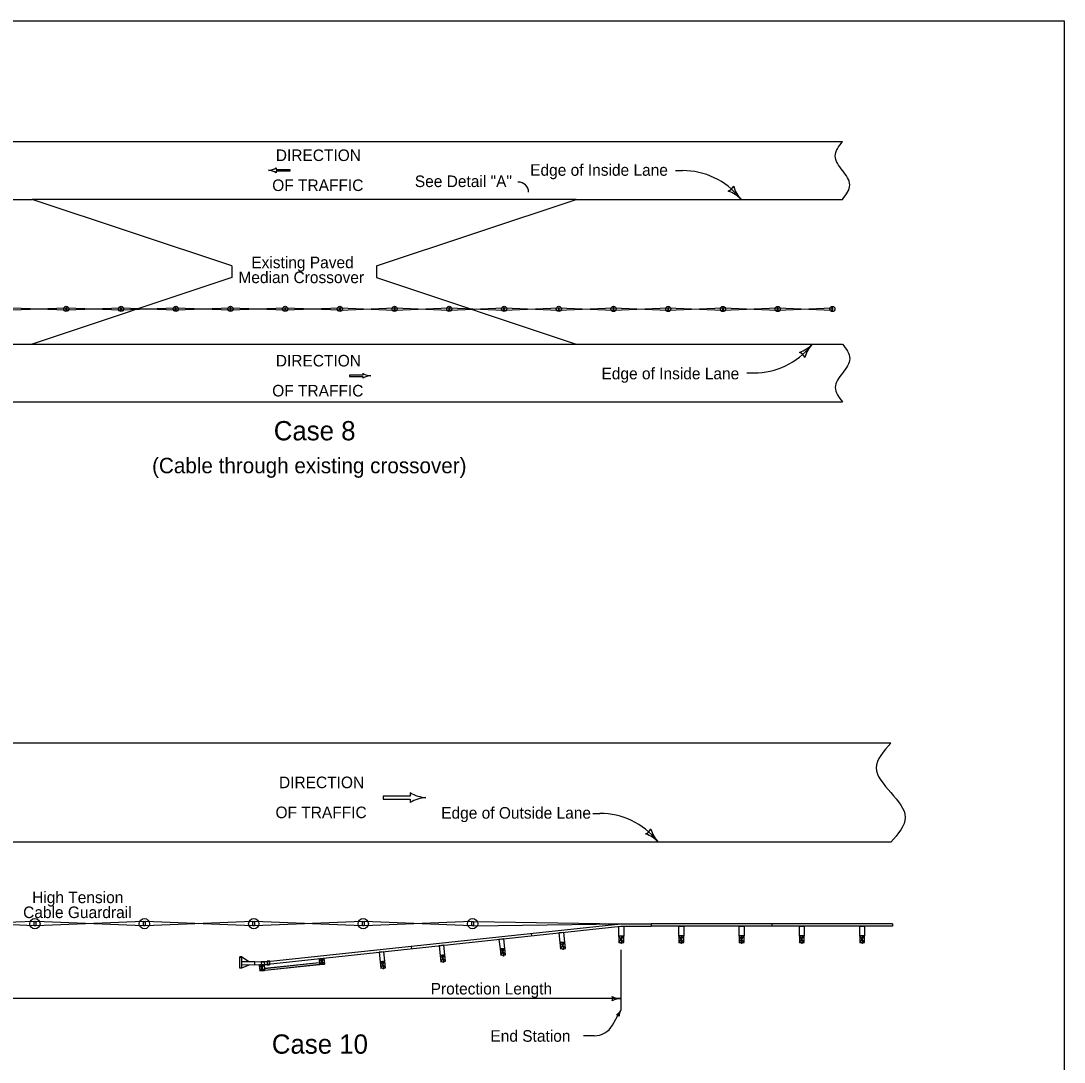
# Model space of a CAD drawing. Extents: x 10133 to 81668, y 7924 to 11018.
# Drawn here: x 15786 to 16868, y 8864 to 9944 of the extents above; entities that cross this region are included whole.
import ezdxf

# ---------------------------------------------------------------- set-up
doc = ezdxf.new("R2010")
doc.units = 0
for name, color, linetype in [('dsnCellElements', 7, 'Continuous'), ('DsnShtRevisedText', 7, 'Continuous'), ('dsnStdDimension', 7, 'Continuous'), ('Level 2', 7, 'Continuous'), ('Level 8', 7, 'Continuous'), ('SheetBorder', 7, 'Continuous')]:
    doc.layers.add(name, color=color, linetype=linetype)

msp = doc.modelspace()

# ---------------------------------------------------------------- linework, layer by layer
at = {"layer": 'dsnCellElements'}
for p, q in [((15777.3, 9644.3), (15833.1, 9646.6)), ((15777.3, 9646.6), (15833.1, 9644.3)), ((15834, 9644.3), (15889.8, 9646.5)), ((15834, 9646.5), (15889.8, 9644.3)), ((15890.7, 9644.3), (15946.5, 9646.5)), ((15890.7, 9646.5), (15946.5, 9644.3)), ((15947.4, 9644.3), (16003.2, 9646.5)), ((15947.4, 9646.5), (16003.2, 9644.3)), ((16004.1, 9644.3), (16059.9, 9646.5)), ((16004.1, 9646.5), (16059.9, 9644.3)), ((16060.8, 9644.3), (16116.6, 9646.5)), ((16060.8, 9646.5), (16116.6, 9644.3)), ((16117.5, 9644.2), (16173.3, 9646.5)), ((16117.5, 9646.5), (16173.3, 9644.2)), ((16174.2, 9644.2), (16230, 9646.5)), ((16174.2, 9646.5), (16230, 9644.2)), ((16230.9, 9644.2), (16286.7, 9646.5)), ((16230.9, 9646.5), (16286.7, 9644.2)), ((16287.6, 9644.2), (16343.4, 9646.5)), ((16287.6, 9646.5), (16343.4, 9644.2)), ((16344.3, 9644.2), (16400.1, 9646.5)), ((16344.3, 9646.5), (16400.1, 9644.2)), ((16401, 9644.2), (16456.8, 9646.5)), ((16401, 9646.5), (16456.8, 9644.2)), ((16457.7, 9644.2), (16513.5, 9646.5)), ((16457.7, 9646.5), (16513.5, 9644.2)), ((16514.4, 9644.2), (16570.2, 9646.5)), ((16514.4, 9646.5), (16570.2, 9644.2)), ((16571.1, 9644.2), (16626.9, 9646.5)), ((16571.1, 9646.5), (16626.9, 9644.2)), ((15800.1, 9005.8), (15688.5, 9010.3)), ((15800.1, 9010.3), (15688.5, 9005.8)), ((15913.5, 9005.8), (15801.9, 9010.3)), ((15913.5, 9010.3), (15801.9, 9005.8)), ((16026.9, 9005.8), (15915.3, 9010.3)), ((16026.9, 9010.3), (15915.3, 9005.8)), ((16140.3, 9005.8), (16028.7, 9010.3)), ((16140.3, 9010.3), (16028.7, 9005.8)), ((16253.7, 9005.8), (16142.1, 9010.3)), ((16253.7, 9010.3), (16142.1, 9005.8)), ((16255.5, 9010.3), (16408.3, 9008)), ((16255.5, 9005.8), (16408.3, 9008))]:
    msp.add_line(p, q, dxfattribs=at)
for points in [[(15833.1, 9646.6), (15833.1, 9644.3), (15834, 9644.3), (15834, 9646.6)], [(15833.1, 9646.5), (15833.1, 9644.3), (15834, 9644.3), (15834, 9646.5)], [(15889.8, 9646.5), (15889.8, 9644.3), (15890.7, 9644.3), (15890.7, 9646.5)], [(15889.8, 9646.5), (15889.8, 9644.3), (15890.7, 9644.3), (15890.7, 9646.5)], [(15946.5, 9646.5), (15946.5, 9644.3), (15947.4, 9644.3), (15947.4, 9646.5)], [(15946.5, 9646.5), (15946.5, 9644.3), (15947.4, 9644.3), (15947.4, 9646.5)], [(16003.2, 9646.5), (16003.2, 9644.3), (16004.1, 9644.3), (16004.1, 9646.5)], [(16003.2, 9646.5), (16003.2, 9644.3), (16004.1, 9644.3), (16004.1, 9646.5)], [(16059.9, 9646.5), (16059.9, 9644.3), (16060.8, 9644.3), (16060.8, 9646.5)], [(16059.9, 9646.5), (16059.9, 9644.3), (16060.8, 9644.3), (16060.8, 9646.5)], [(16116.6, 9646.5), (16116.6, 9644.3), (16117.5, 9644.3), (16117.5, 9646.5)], [(16116.6, 9646.5), (16116.6, 9644.2), (16117.5, 9644.2), (16117.5, 9646.5)], [(16173.3, 9646.5), (16173.3, 9644.2), (16174.2, 9644.2), (16174.2, 9646.5)], [(16173.3, 9646.5), (16173.3, 9644.2), (16174.2, 9644.2), (16174.2, 9646.5)], [(16230, 9646.5), (16230, 9644.2), (16230.9, 9644.2), (16230.9, 9646.5)], [(16230, 9646.5), (16230, 9644.2), (16230.9, 9644.2), (16230.9, 9646.5)], [(16286.7, 9646.5), (16286.7, 9644.2), (16287.6, 9644.2), (16287.6, 9646.5)], [(16286.7, 9646.5), (16286.7, 9644.2), (16287.6, 9644.2), (16287.6, 9646.5)], [(16343.4, 9646.5), (16343.4, 9644.2), (16344.3, 9644.2), (16344.3, 9646.5)], [(16343.4, 9646.5), (16343.4, 9644.2), (16344.3, 9644.2), (16344.3, 9646.5)], [(16400.1, 9646.5), (16400.1, 9644.2), (16401, 9644.2), (16401, 9646.5)], [(16400.1, 9646.5), (16400.1, 9644.2), (16401, 9644.2), (16401, 9646.5)], [(16456.8, 9646.5), (16456.8, 9644.2), (16457.7, 9644.2), (16457.7, 9646.5)], [(16456.8, 9646.5), (16456.8, 9644.2), (16457.7, 9644.2), (16457.7, 9646.5)], [(16513.5, 9646.5), (16513.5, 9644.2), (16514.4, 9644.2), (16514.4, 9646.5)], [(16513.5, 9646.5), (16513.5, 9644.2), (16514.4, 9644.2), (16514.4, 9646.5)], [(16570.2, 9646.5), (16570.2, 9644.2), (16571.1, 9644.2), (16571.1, 9646.5)], [(16570.2, 9646.5), (16570.2, 9644.2), (16571.1, 9644.2), (16571.1, 9646.5)], [(16626.9, 9646.5), (16626.9, 9644.2), (16627.8, 9644.2), (16627.8, 9646.5)], [(15801.9, 9010.3), (15801.9, 9005.8), (15800.1, 9005.8), (15800.1, 9010.3)], [(15801.9, 9010.3), (15801.9, 9005.8), (15800.1, 9005.8), (15800.1, 9010.3)], [(15915.3, 9010.3), (15915.3, 9005.8), (15913.5, 9005.8), (15913.5, 9010.3)], [(15915.3, 9010.3), (15915.3, 9005.8), (15913.5, 9005.8), (15913.5, 9010.3)], [(16028.7, 9010.3), (16028.7, 9005.8), (16026.9, 9005.8), (16026.9, 9010.3)], [(16028.7, 9010.3), (16028.7, 9005.8), (16026.9, 9005.8), (16026.9, 9010.3)], [(16142.1, 9010.3), (16142.1, 9005.8), (16140.3, 9005.8), (16140.3, 9010.3)], [(16142.1, 9010.3), (16142.1, 9005.8), (16140.3, 9005.8), (16140.3, 9010.3)], [(16255.5, 9010.3), (16255.5, 9005.8), (16253.7, 9005.8), (16253.7, 9010.3)]]:
    msp.add_lwpolyline(points, close=True, dxfattribs=at)
for centre, radius in [((15833.5, 9645.4), 2.66), ((15833.5, 9645.4), 2.66), ((15890.2, 9645.4), 2.66), ((15890.2, 9645.4), 2.66), ((15946.9, 9645.4), 2.66), ((15946.9, 9645.4), 2.66), ((16003.6, 9645.4), 2.66), ((16003.6, 9645.4), 2.66), ((16060.3, 9645.4), 2.66), ((16060.3, 9645.4), 2.66), ((16117, 9645.4), 2.66), ((16117, 9645.4), 2.66), ((16173.7, 9645.4), 2.66), ((16173.7, 9645.4), 2.66), ((16230.4, 9645.4), 2.66), ((16230.4, 9645.4), 2.66), ((16287.2, 9645.4), 2.66), ((16287.2, 9645.4), 2.66), ((16343.9, 9645.4), 2.66), ((16343.9, 9645.4), 2.66), ((16400.6, 9645.4), 2.66), ((16400.6, 9645.3), 2.66), ((16457.3, 9645.3), 2.66), ((16457.3, 9645.3), 2.66), ((16514, 9645.3), 2.66), ((16514, 9645.3), 2.66), ((16570.7, 9645.3), 2.66), ((16570.7, 9645.3), 2.66), ((16627.4, 9645.3), 2.66), ((15801, 9008), 5.32), ((15801, 9008), 5.32), ((15914.4, 9008), 5.32), ((15914.4, 9008), 5.32), ((16027.8, 9008), 5.32), ((16027.8, 9008), 5.32), ((16141.2, 9008), 5.32), ((16141.2, 9008), 5.32), ((16254.6, 9008), 5.32)]:
    msp.add_circle(centre, radius, dxfattribs=at)
at = {"layer": 'DsnShtRevisedText'}
for p, q in [((16043, 9789.1), (16043, 9789.1)), ((16051.1, 9791.6), (16051.1, 9789.8)), ((16051.1, 9789.8), (16065, 9789.8)), ((16065, 9788.3), (16051.1, 9788.3)), ((16051.1, 9788.3), (16051.1, 9786.5)), ((16065, 9789.8), (16065, 9788.3)), ((16464.7, 9788.8), (16472.2, 9788.8)), ((16140.9, 9578.6), (16140.9, 9576.8)), ((16538.6, 9579), (16546.1, 9579)), ((16140.9, 9576.8), (16126.9, 9576.8)), ((16126.9, 9576.8), (16126.9, 9575.3)), ((16126.9, 9575.3), (16140.9, 9575.3)), ((16140.9, 9575.3), (16140.9, 9573.5)), ((16149, 9576.1), (16149, 9576.1)), ((16190, 9140.3), (16162, 9140.3)), ((16162, 9140.3), (16162, 9137.2)), ((16162, 9137.2), (16190, 9137.2)), ((16190, 9143.8), (16190, 9140.3)), ((16190, 9137.2), (16190, 9133.7)), ((16206.2, 9138.7), (16206.2, 9138.7)), ((16379, 9122.3), (16386.5, 9122.3)), ((16408.2, 8980.9), (16408.2, 8918.3)), ((16385.8, 8930.3), (15702.8, 8930.3)), ((16408.2, 8930.3), (16385.8, 8930.3)), ((16399.4, 8902.7), (16408.2, 8918.3)), ((16380.6, 8891.9), (16369.3, 8891.9))]:
    msp.add_line(p, q, dxfattribs=at)
for centre, radius, start, end in [((16042.3, 9805.4), 16.4, 272.352, 302.382), ((16042.3, 9772.7), 16.4, 57.618, 87.648), ((16472.2, 9712.6), 76.2, 39.0106, 90), ((16301.8, 9766.1), 10.8, 1.4994, 91.4994), ((16514.2, 9778.7), 12.5, 295.2639, 330.7306), ((16509, 9736.8), 32.4, 42.9973, 71.0698), ((16556.4, 9781), 32.4, 194.9248, 222.9973), ((16546.1, 9655.2), 76.2, 270, 320.9894), ((16582.9, 9631), 32.4, 288.9302, 317.0027), ((16588.1, 9589), 12.5, 29.2694, 64.7361), ((16630.3, 9586.8), 32.4, 137.0027, 165.0752), ((16149.7, 9592.4), 16.4, 237.618, 267.648), ((16149.7, 9559.7), 16.4, 92.352, 122.382), ((16207.5, 9171.5), 32.7, 237.618, 267.648), ((16207.5, 9106), 32.7, 92.352, 122.382), ((16386.5, 9046.1), 76.2, 39.0106, 90), ((16428.5, 9112.3), 12.5, 295.2639, 330.7306), ((16470.7, 9114.5), 32.4, 194.9248, 222.9973), ((16423.3, 9070.4), 32.4, 42.9973, 71.0698), ((16392.2, 8930.3), 7.39, 342.2666, 17.7333), ((16408.2, 8949.4), 19.1, 241.9275, 270), ((16408.2, 8911.2), 19.1, 90, 118.0725), ((16396.5, 8925.2), 13.6, 301.6962, 329.7686), ((16402.5, 8908.5), 5.25, 42.0353, 77.502), ((16420, 8911.5), 13.6, 149.7686, 177.8411), ((16380.6, 8913.6), 21.8, 270, 329.7757)]:
    msp.add_arc(centre, radius, start, end, dxfattribs=at)
at = {"layer": 'dsnStdDimension'}
for p, q in [((15522.2, 9818.9), (16637.9, 9818.9)), ((15522.2, 9758.9), (15798, 9758.9)), ((16005, 9689.9), (15798, 9758.9)), ((16362, 9758.9), (15798, 9758.9)), ((16155, 9689.9), (16362, 9758.9)), ((16358.9, 9758.9), (16637.9, 9758.9)), ((16005, 9689.9), (16005, 9677.9)), ((16155, 9689.9), (16155, 9677.9)), ((16005, 9677.9), (15798, 9608.9)), ((16155, 9677.9), (16362, 9608.9)), ((15522.2, 9608.9), (15801.1, 9608.9)), ((15801.1, 9608.9), (16362, 9608.9)), ((16362, 9608.9), (16637.9, 9608.9)), ((15522.2, 9548.9), (16637.9, 9548.9)), ((16687.9, 9195.3), (15467.4, 9195.3)), ((16687.9, 9092.4), (15467.4, 9092.4))]:
    msp.add_line(p, q, dxfattribs=at)
for points in [[(16637.9, 9758.9), (16645.4, 9773.9), (16637.9, 9788.9), (16630.4, 9803.9), (16637.9, 9818.9)], [(16637.9, 9608.9), (16645.4, 9593.9), (16637.9, 9578.9), (16630.4, 9563.9), (16637.9, 9548.9)], [(16687.9, 9195.3), (16672.9, 9169.6), (16687.9, 9143.9), (16702.9, 9118.2), (16687.9, 9092.4)]]:
    msp.add_spline(points, degree=3, dxfattribs=at)
at = {"layer": 'Level 2'}
for p, q in [((16035.4, 8968), (16408.3, 9008)), ((16408.3, 9008), (16439.6, 9008)), ((16439.6, 9008), (16439.6, 9005.3)), ((16564.6, 9008), (16439.6, 9008)), ((16439.6, 9008), (16439.6, 9005.3)), ((16564.6, 9008), (16564.6, 9005.3)), ((16689.6, 9008), (16564.6, 9008)), ((16564.6, 9008), (16564.6, 9005.3)), ((16689.6, 9008), (16689.6, 9005.3)), ((16035.7, 8965.3), (16408.3, 9005.3)), ((16315.2, 8998), (16315.5, 8995.3)), ((16406.2, 9005.1), (16411.2, 9005.3)), ((16406.2, 8995.1), (16406.2, 9005.1)), ((16411.2, 8995.1), (16406.2, 8995.1)), ((16411.2, 8988.4), (16406.2, 8995.1)), ((16406.2, 8988.4), (16411.2, 8995.1)), ((16408.3, 9005.3), (16439.6, 9005.3)), ((16408.7, 8995.1), (16408.7, 8988.4)), ((16411.2, 9005.3), (16411.2, 8995.1)), ((16564.6, 9005.3), (16439.6, 9005.3)), ((16468.3, 8995.3), (16468.3, 9005.3)), ((16468.3, 9005.3), (16473.3, 9005.3)), ((16473.3, 8995.3), (16468.3, 8995.3)), ((16473.3, 8988.6), (16468.3, 8995.3)), ((16468.3, 8988.6), (16473.3, 8995.3)), ((16470.8, 8995.3), (16470.8, 8988.6)), ((16473.3, 9005.3), (16473.3, 8995.3)), ((16530.8, 8995.3), (16530.8, 9005.3)), ((16530.8, 9005.3), (16535.8, 9005.3)), ((16535.8, 8995.3), (16530.8, 8995.3)), ((16535.8, 8988.6), (16530.8, 8995.3)), ((16530.8, 8988.6), (16535.8, 8995.3)), ((16533.3, 8995.3), (16533.3, 8988.6)), ((16535.8, 9005.3), (16535.8, 8995.3)), ((16689.6, 9005.3), (16564.6, 9005.3)), ((16593.3, 8995.3), (16593.3, 9005.3)), ((16593.3, 9005.3), (16598.3, 9005.3)), ((16598.3, 8995.3), (16593.3, 8995.3)), ((16598.3, 8988.6), (16593.3, 8995.3)), ((16593.3, 8988.6), (16598.3, 8995.3)), ((16595.8, 8995.3), (16595.8, 8988.6)), ((16598.3, 9005.3), (16598.3, 8995.3)), ((16655.8, 8995.3), (16655.8, 9005.3)), ((16655.8, 9005.3), (16660.8, 9005.3)), ((16660.8, 8995.3), (16655.8, 8995.3)), ((16660.8, 8988.6), (16655.8, 8995.3)), ((16655.8, 8988.6), (16660.8, 8995.3)), ((16658.3, 8995.3), (16658.3, 8988.6)), ((16660.8, 9005.3), (16660.8, 8995.3)), ((16190.9, 8984.7), (16191.2, 8982)), ((16350.8, 8982.4), (16345.1, 8988.5)), ((16345.8, 8981.8), (16350.1, 8989)), ((16347.6, 8988.7), (16348.3, 8982.1)), ((16470.8, 8987.6), (16470.8, 8987.6)), ((16533.3, 8987.6), (16533.3, 8987.6)), ((16595.8, 8987.6), (16595.8, 8987.6)), ((16658.3, 8987.6), (16658.3, 8987.6)), ((16226.5, 8969), (16220.8, 8975.1)), ((16221.5, 8968.5), (16225.8, 8975.6)), ((16223.3, 8975.4), (16224, 8968.7)), ((16288.7, 8975.7), (16283, 8981.8)), ((16283.7, 8975.2), (16287.9, 8982.3)), ((16285.5, 8982), (16286.2, 8975.4)), ((16286.3, 8974.5), (16286.3, 8974.4)), ((16286.6, 8975.4), (16286.7, 8975.4)), ((16348.4, 8981.1), (16348.4, 8981)), ((16028.9, 8968.3), (16041.5, 8968.8)), ((16041.6, 8965.7), (16029, 8965.1)), ((16034.2, 8965.2), (16034.3, 8965)), ((16035.4, 8968), (16035.7, 8965.3)), ((16035.8, 8965.2), (16036.5, 8959.4)), ((16038.7, 8968.7), (16038.8, 8965.5)), ((16039.1, 8959.8), (16095.9, 8965.9)), ((16096.6, 8971.9), (16100.4, 8972.3)), ((16098, 8972), (16098.6, 8966)), ((16164.4, 8962.3), (16158.7, 8968.4)), ((16159.4, 8961.8), (16163.7, 8969)), ((16161.2, 8968.7), (16161.9, 8962.1)), ((16224.1, 8967.8), (16224.1, 8967.7)), ((16162, 8961.1), (16162, 8961))]:
    msp.add_line(p, q, dxfattribs=at)
for points in [[(16349, 8998.9), (16344, 8998.4), (16345.1, 8988.5), (16350.1, 8989)], [(16411.2, 8995.1), (16406.2, 8995.1), (16406.2, 8988.4), (16411.2, 8988.4)], [(16473.3, 8995.3), (16468.3, 8995.3), (16468.3, 8988.6), (16473.3, 8988.6)], [(16535.8, 8995.3), (16530.8, 8995.3), (16530.8, 8988.6), (16535.8, 8988.6)], [(16598.3, 8995.3), (16593.3, 8995.3), (16593.3, 8988.6), (16598.3, 8988.6)], [(16660.8, 8995.3), (16655.8, 8995.3), (16655.8, 8988.6), (16660.8, 8988.6)], [(16224.7, 8985.6), (16219.8, 8985.1), (16220.8, 8975.1), (16225.8, 8975.6)], [(16286.9, 8992.3), (16281.9, 8991.7), (16283, 8981.8), (16287.9, 8982.3)], [(16350.1, 8989), (16345.1, 8988.5), (16345.8, 8981.8), (16350.8, 8982.4)], [(16162.6, 8978.9), (16157.6, 8978.4), (16158.7, 8968.4), (16163.7, 8969)], [(16225.8, 8975.6), (16220.8, 8975.1), (16221.5, 8968.5), (16226.5, 8969)], [(16287.9, 8982.3), (16283, 8981.8), (16283.7, 8975.2), (16288.7, 8975.7)], [(16041.6, 8965.5), (16041.6, 8965.2), (16044.1, 8965.3), (16044.1, 8965.6), (16044, 8969.1), (16044, 8969.4), (16041.5, 8969.3), (16041.5, 8969)], [(16163.7, 8969), (16158.7, 8968.4), (16159.4, 8961.8), (16164.4, 8962.3)]]:
    msp.add_lwpolyline(points, close=True, dxfattribs=at)
for points in [[(16409, 8988.4), (16409, 8988), (16408.4, 8988), (16408.4, 8988.4)], [(16408.9, 8988), (16408.9, 8987.5), (16408.5, 8987.5), (16408.5, 8988)], [(16471.1, 8988.6), (16471.1, 8988.2), (16470.5, 8988.2), (16470.5, 8988.6)], [(16471, 8988.2), (16471, 8987.6), (16470.6, 8987.6), (16470.6, 8988.2)], [(16533.6, 8988.6), (16533.6, 8988.2), (16533, 8988.2), (16533, 8988.6)], [(16533.5, 8988.2), (16533.5, 8987.6), (16533.1, 8987.6), (16533.1, 8988.2)], [(16596.1, 8988.6), (16596.1, 8988.2), (16595.5, 8988.2), (16595.5, 8988.6)], [(16596, 8988.2), (16596, 8987.6), (16595.6, 8987.6), (16595.6, 8988.2)], [(16658.6, 8988.6), (16658.6, 8988.2), (16658, 8988.2), (16658, 8988.6)], [(16658.5, 8988.2), (16658.5, 8987.6), (16658.1, 8987.6), (16658.1, 8988.2)], [(16013.3, 8961.8), (16013.4, 8973.5)], [(16013.4, 8973.4), (16015, 8973.3), (16014.9, 8961.9), (16013.3, 8961.9)], [(16015.1, 8973.5), (16013.4, 8973.5)], [(16015.1, 8973.5), (16015, 8961.8)], [(16022.5, 8968.5), (16015.1, 8973.5)], [(16286.5, 8975.5), (16286.5, 8975), (16285.9, 8975), (16285.8, 8975.4)], [(16286.4, 8975), (16286.5, 8974.5), (16286.1, 8974.4), (16286, 8975)], [(16348.6, 8982.1), (16348.7, 8981.7), (16348, 8981.6), (16348, 8982)], [(16348.5, 8981.7), (16348.6, 8981.1), (16348.2, 8981.1), (16348.2, 8981.6)], [(16029, 8965), (16015, 8965.2)], [(16022.6, 8965.1), (16015, 8961.8)], [(16028.9, 8968.5), (16015.1, 8968.6)], [(16041.6, 8965.5), (16029, 8965), (16028.9, 8968.5), (16041.5, 8969)], [(16033.3, 8964.9), (16038.3, 8965.4)], [(16033.3, 8964.9), (16038.9, 8959.6)], [(16033.3, 8964.9), (16034, 8959.1)], [(16038.3, 8965.4), (16034, 8959.1)], [(16038.3, 8965.6), (16034.2, 8965.2)], [(16038.3, 8965.4), (16034.3, 8965)], [(16038.4, 8965.4), (16038.4, 8965)], [(16038.4, 8965), (16038.4, 8964.8)], [(16038.4, 8964.8), (16038.8, 8961.9)], [(16038.5, 8965.4), (16038.6, 8965)], [(16038.6, 8965), (16038.6, 8964.8)], [(16038.6, 8964.8), (16038.9, 8961.9)], [(16038.9, 8961.8), (16095.7, 8967.9)], [(16038.9, 8961.7), (16095.7, 8967.8)], [(16039.2, 8959.7), (16095.9, 8965.8)], [(16041.5, 8969), (16044, 8969.1), (16044.1, 8965.6), (16041.6, 8965.5)], [(16095.3, 8971.5), (16095.4, 8971.1)], [(16095.4, 8971.1), (16095.9, 8965.8)], [(16095.5, 8971.7), (16100.5, 8972.3)], [(16095.5, 8971.6), (16100.5, 8972.1)], [(16095.5, 8971.6), (16101.1, 8966.3)], [(16095.5, 8971.6), (16095.5, 8971.1)], [(16095.5, 8971.1), (16096.1, 8965.8)], [(16100.5, 8972.1), (16096.1, 8965.8)], [(16096.1, 8965.8), (16101.1, 8966.3)], [(16096.2, 8965.6), (16101.1, 8966.2)], [(16100.5, 8972.3), (16101.1, 8966.2)], [(16224.4, 8968.8), (16224.4, 8968.4), (16223.7, 8968.3), (16223.7, 8968.7)], [(16224.3, 8968.3), (16224.3, 8967.8), (16223.9, 8967.8), (16223.9, 8968.3)], [(16015, 8961.8), (16013.3, 8961.8)], [(16034, 8959.1), (16038.9, 8959.6)], [(16038.9, 8959.6), (16034.9, 8959.2)], [(16039, 8959.5), (16034.9, 8959)], [(16034.9, 8959), (16034.9, 8959.2)], [(16038.8, 8961.9), (16039, 8959.7)], [(16038.9, 8961.9), (16039.2, 8959.7)], [(16162.2, 8962.1), (16162.3, 8961.7), (16161.6, 8961.6), (16161.5, 8962)], [(16162.1, 8961.7), (16162.2, 8961.1), (16161.8, 8961.1), (16161.7, 8961.6)]]:
    msp.add_lwpolyline(points, dxfattribs=at)
for centre, radius, start, end in [((16038.3, 8965.4), 0.208, 6.1292, 96.1292), ((16038.3, 8965.4), 0.0517, 6.1292, 96.1292), ((16095.5, 8971.5), 0.208, 96.1292, 186.1292), ((16096.1, 8965.8), 0.208, 186.1292, 276.1292), ((16038.9, 8959.7), 0.0517, 276.1292, 6.1292), ((16038.9, 8959.7), 0.208, 276.1292, 6.1292)]:
    msp.add_arc(centre, radius, start, end, dxfattribs=at)
at = {"layer": 'SheetBorder'}
msp.add_lwpolyline([(13732.5, 9944), (16867.5, 9944), (16867.5, 7924), (13732.5, 7924)], close=True, dxfattribs=at)

# ---------------------------------------------------------------- texts
at = {"layer": 'DsnShtRevisedText'}
for s, p in [('DIRECTION', (16050.6, 9798.7)), ('Edge of Inside Lane', (16314.2, 9783.4)), ('See Detail "A"', (16194.7, 9771.7)), ('OF TRAFFIC', (16046.9, 9767.6)), ('Existing Paved', (16025.2, 9687.6)), ('Median Crossover', (16011.9, 9672.1)), ('DIRECTION', (16050.6, 9585.7)), ('Edge of Inside Lane', (16388.1, 9572.4)), ('OF TRAFFIC', (16046.9, 9554.6)), ('DIRECTION', (16053.9, 9148.5)), ('OF TRAFFIC', (16050.3, 9117.4)), ('Edge of Outside Lane', (16222, 9116.9)), ('High Tension', (15798.1, 9029.3)), ('Cable Guardrail', (15788.8, 9013.8)), ('Protection Length', (16211.1, 8934.6)), ('End Station', (16273, 8885.6))]:
    msp.add_text(s, height=12, dxfattribs=at).set_placement(p)
at = {"layer": 'Level 8'}
for s, height, p in [('Case 8', 20, (16048.5, 9509.1)), ('(Cable through existing crossover)', 16, (15922.4, 9475)), ('Case 10', 20, (16046.5, 8873.2))]:
    msp.add_text(s, height=height, dxfattribs=at).set_placement(p)

doc.saveas('drawing.dxf')
